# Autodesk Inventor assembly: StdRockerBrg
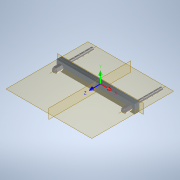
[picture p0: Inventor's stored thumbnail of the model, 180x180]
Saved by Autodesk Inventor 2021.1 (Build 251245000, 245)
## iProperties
RuleStatus: InUse
Created: 2019-05
Part Number: StdRockerBrg
Document SubType Name: Assembly
Designer: u1426
AnchorBoltEmbed: 15.000 in
MasonryPLThickness: 1.500 in
SolePLThickness: 1.250 in
BearingLength: 44.000 in
NoSwedges: 4.000 in
ExpansionCapLength: 24.000 in
AnchorDiameter: 1.750 in
AnchorEdgeDist: 2.500 in
BearingWidth: 5.000 in
Author: u1426
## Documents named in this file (11)
- C:\Users\u4092\Desktop\TrevinOldBridge\StdRockerBrg\StdRockerBrg.iam
- C:\Users\u4092\Desktop\TrevinOldBridge\StdRockerBrg\IW_Export\StdRockerBrgMasonry.ipt
- C:\Users\u4092\Desktop\TrevinOldBridge\StdRockerBrg\IW_Export\StdRockerBrgSole.ipt
- C:\Users\u4092\Desktop\TrevinOldBridge\StdRockerBrg\IW_Export\AnchorBolt.ipt
- C:\Users\u4092\Desktop\TrevinOldBridge\StdRockerBrg\IW_Export\ANSI B18.2.2 - 1 1_2 - 6(8).ipt
- C:\Users\u4092\Desktop\TrevinOldBridge\StdRockerBrg\IW_Export\ANSI B18.2.2 - 1 - 8(8).ipt
- C:\Users\u4092\Desktop\TrevinOldBridge\StdRockerBrg\IW_Export\ANSI B18.2.2 - 1 1_4 - 7(8).ipt
- C:\Users\u4092\Desktop\TrevinOldBridge\StdRockerBrg\IW_Export\ANSI B18.2.2 - 1 3_4 - 5(8).ipt
- C:\Users\u4092\Desktop\TrevinOldBridge\StdRockerBrg\IW_Export\ANSI B18.2.2 - 2 - 4 1_2(8).ipt
- C:\Users\u4092\Desktop\TrevinOldBridge\StdRockerBrg\IW_Export\ExpansionCap.ipt
- C:\Users\u4092\Desktop\TrevinOldBridge\StdRockerBrg\StdRockerShim.ipt
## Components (27 placed, 10 different names)
1. StdRockerBrgMasonry:1 — Flush:3, Flush:4, Mate:4, Mate:5, Flush:5, Flush:6, Flush:7, Flush:8, Flush:9, Flush:10, Flush:29, Mate:29, Mate:30, Flush:12, Mate to UCSXY, Mate to USCXZ, Mate to USCYZ, Mate:34, Flush:30, Flush:31
2. StdRockerBrgSole:1 — Mate:1, Flush:11, Flush:29
3. AnchorBolt:1 — Flush:3, Mate:4, Mate:7, Mate:13, Mate:17, Mate:21, Mate:25, Mate:29
4. AnchorBolt:2 — Flush:4, Mate:5, Mate:11, Mate:15, Mate:19, Mate:23, Mate:27, Mate:30
5. Heavy Hex Nut - Inch 1 - 8:1 — Mate:13
6. Heavy Hex Nut - Inch 1 - 8:2
7. Heavy Hex Nut - Inch 1 - 8:3 — Mate:15
8. Heavy Hex Nut - Inch 1 - 8:4
9. Heavy Hex Nut - Inch 1 1/4 - 7:1 — Mate:17
10. Heavy Hex Nut - Inch 1 1/4 - 7:2
11. Heavy Hex Nut - Inch 1 1/4 - 7:3 — Mate:19
12. Heavy Hex Nut - Inch 1 1/4 - 7:4
13. Heavy Hex Nut - Inch 1 1/2 - 6:1 — Mate:7, Mate:9
14. Heavy Hex Nut - Inch 1 1/2 - 6:2 — Mate:9
15. Heavy Hex Nut - Inch 1 1/2 - 6:3 — Mate:11
16. Heavy Hex Nut - Inch 1 1/2 - 6:4
17. Heavy Hex Nut - Inch 1 3/4 - 5:1 — Mate:21
18. Heavy Hex Nut - Inch 1 3/4 - 5:2
19. Heavy Hex Nut - Inch 1 3/4 - 5:3 — Mate:23
20. Heavy Hex Nut - Inch 1 3/4 - 5:4
21. Heavy Hex Nut - Inch 2 - 4 1/2:1 — Mate:25
22. Heavy Hex Nut - Inch 2 - 4 1/2:2
23. Heavy Hex Nut - Inch 2 - 4 1/2:3 — Mate:27
24. Heavy Hex Nut - Inch 2 - 4 1/2:4
25. ExpansionCap:1 — Flush:5, Flush:7, Flush:9
26. ExpansionCap:2 — Flush:6, Flush:8, Flush:10
27. StdRockerShim:1 — Mate:34, Flush:30, Flush:31
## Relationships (33: Mate 20, Flush 13)
- Mate:1: StdRockerBrgSole:1
- Flush:3: StdRockerBrgMasonry:1 ↔ AnchorBolt:1
- Flush:4: StdRockerBrgMasonry:1 ↔ AnchorBolt:2
- Mate:4: StdRockerBrgMasonry:1 ↔ AnchorBolt:1
- Mate:5: StdRockerBrgMasonry:1 ↔ AnchorBolt:2
- Mate:7: AnchorBolt:1 ↔ Heavy Hex Nut - Inch 1 1/2 - 6:1
- Mate:9: Heavy Hex Nut - Inch 1 1/2 - 6:1 ↔ Heavy Hex Nut - Inch 1 1/2 - 6:2
- Mate:11: AnchorBolt:2 ↔ Heavy Hex Nut - Inch 1 1/2 - 6:3
- Mate:13: AnchorBolt:1 ↔ Heavy Hex Nut - Inch 1 - 8:1
- Mate:15: AnchorBolt:2 ↔ Heavy Hex Nut - Inch 1 - 8:3
- Mate:17: AnchorBolt:1 ↔ Heavy Hex Nut - Inch 1 1/4 - 7:1
- Mate:19: AnchorBolt:2 ↔ Heavy Hex Nut - Inch 1 1/4 - 7:3
- Mate:21: AnchorBolt:1 ↔ Heavy Hex Nut - Inch 1 3/4 - 5:1
- Mate:23: AnchorBolt:2 ↔ Heavy Hex Nut - Inch 1 3/4 - 5:3
- Mate:25: AnchorBolt:1 ↔ Heavy Hex Nut - Inch 2 - 4 1/2:1
- Mate:27: AnchorBolt:2 ↔ Heavy Hex Nut - Inch 2 - 4 1/2:3
- Flush:5: StdRockerBrgMasonry:1 ↔ ExpansionCap:1
- Flush:6: StdRockerBrgMasonry:1 ↔ ExpansionCap:2
- Flush:7: StdRockerBrgMasonry:1 ↔ ExpansionCap:1
- Flush:8: StdRockerBrgMasonry:1 ↔ ExpansionCap:2
- Flush:9: StdRockerBrgMasonry:1 ↔ ExpansionCap:1
- Flush:10: StdRockerBrgMasonry:1 ↔ ExpansionCap:2
- Flush:11: StdRockerBrgSole:1
- Flush:29: StdRockerBrgMasonry:1 ↔ StdRockerBrgSole:1
- Mate:29: StdRockerBrgMasonry:1 ↔ AnchorBolt:1
- Mate:30: StdRockerBrgMasonry:1 ↔ AnchorBolt:2
- Flush:12: StdRockerBrgMasonry:1
- Mate to UCSXY: StdRockerBrgMasonry:1
- Mate to USCXZ: StdRockerBrgMasonry:1
- Mate to USCYZ: StdRockerBrgMasonry:1
- Mate:34: StdRockerBrgMasonry:1 ↔ StdRockerShim:1
- Flush:30: StdRockerBrgMasonry:1 ↔ StdRockerShim:1
- Flush:31: StdRockerBrgMasonry:1 ↔ StdRockerShim:1
## Named parameters: EmbedConcrete = 381 mm, Protrusion = 177.8 mm, USC1_X = 0, USC1_Y = 0, USC1_Z = 0, USC1_RX = 0, USC1_RY = 0, USC1_RZ = 0
